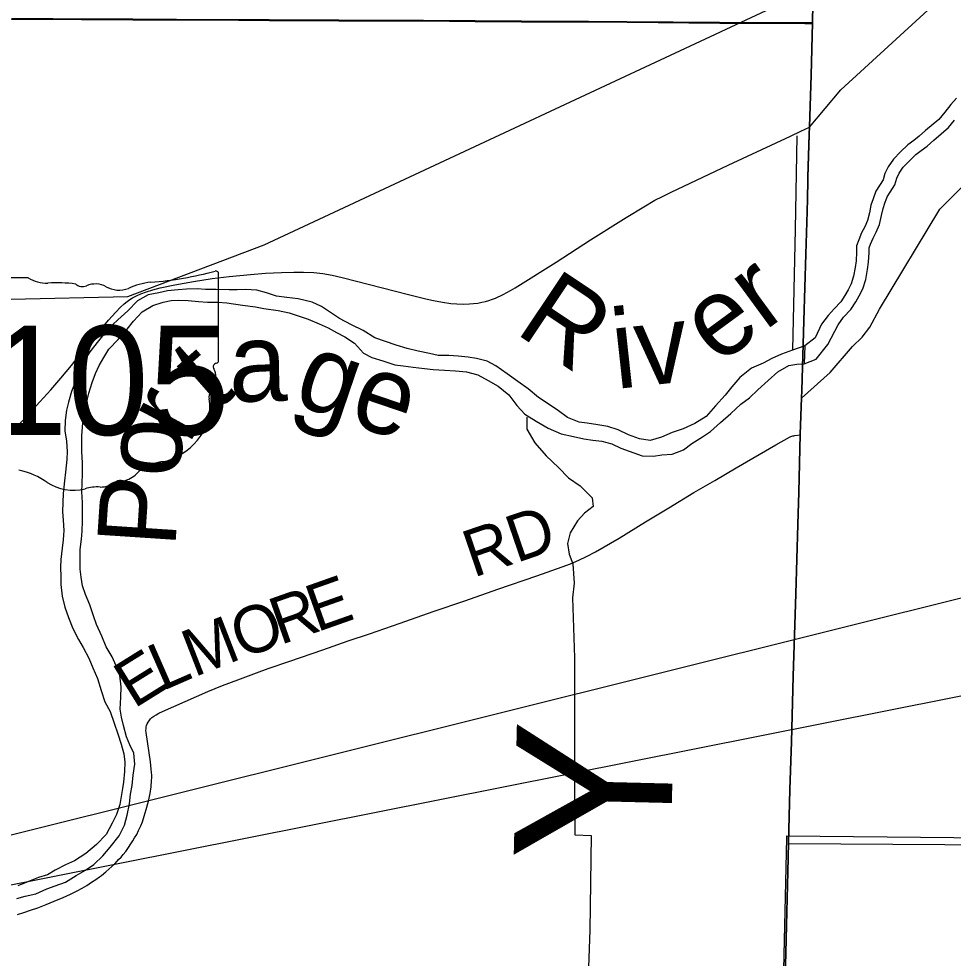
# Model space of a CAD drawing. Extents: x 0 to 34, y 0 to 22.
# Drawn here: x 6.172 to 7.301, y 17.366 to 18.499 of the extents above; entities that cross this region are included whole.
import ezdxf

# ---------------------------------------------------------------- set-up
doc = ezdxf.new("R2010")
doc.units = 0
for name, color, linetype in [('Default', 7, 'Continuous'), ('GM_X_County_Road', 7, 'Continuous'), ('GM_X_County_Text', 7, 'Continuous'), ('GM_X_Major_River', 7, 'Continuous'), ('GM_X_Major_River_Text', 7, 'Continuous'), ('GM_X_Minor_River', 7, 'Continuous'), ('GM_X_Rail_Line', 7, 'Continuous'), ('GM_X_Section', 7, 'Continuous'), ('GM_X_State_Location', 7, 'Continuous'), ('GM_X_State_Route', 7, 'Continuous'), ('GM_X_State_Shield', 7, 'Continuous'), ('GM_X_Township_Road', 7, 'Continuous'), ('GM_X_Township_Road_Text', 7, 'Continuous'), ('GM_X_US_Route', 7, 'Continuous'), ('SH_Cut_Line', 7, 'Continuous'), ('SH_Text', 7, 'Continuous')]:
    doc.layers.add(name, color=color, linetype=linetype)

msp = doc.modelspace()

# ---------------------------------------------------------------- linework, layer by layer
at = {"layer": 'Default'}
for points in [[(6.164, 18.4994), (6.2138, 18.4993), (6.2479, 18.4991), (6.2852, 18.4989), (6.3101, 18.4989), (6.3629, 18.4987), (6.4375, 18.4981), (6.4748, 18.498), (6.5588, 18.4976), (6.6613, 18.4974), (6.7235, 18.4969), (6.7794, 18.4965), (6.8603, 18.4961), (6.9069, 18.4959), (7.0188, 18.4948), (7.0871, 18.4945), (7.1214, 18.4945), (7.1309, 18.4945), (7.1309, 18.4967), (7.1325, 18.5729)], [(7.1325, 18.5729), (7.1309, 18.4967), (7.1309, 18.4945), (7.1292, 18.4315), (7.1272, 18.3691), (7.1269, 18.36), (7.1254, 18.3087), (7.1253, 18.3041), (7.1248, 18.2823), (7.1245, 18.2668), (7.1228, 18.2155), (7.1205, 18.1347), (7.118, 18.0508), (7.1177, 18.0419), (7.1163, 17.998), (7.1163, 17.9976), (7.1144, 17.9281), (7.1133, 17.8892), (7.1108, 17.8053), (7.1078, 17.7059), (7.1055, 17.6267), (7.1037, 17.5692), (7.1025, 17.521), (7.102, 17.5046), (7.1011, 17.4697), (7.0999, 17.4216), (7.0987, 17.3718), (7.096, 17.2678)], [(7.096, 17.2678), (7.0987, 17.3718), (7.0999, 17.4216), (7.1011, 17.4697), (7.102, 17.5046), (7.1025, 17.521), (7.1037, 17.5692), (7.1055, 17.6267), (7.1078, 17.7059), (7.1108, 17.8053), (7.1133, 17.8892), (7.1144, 17.9281), (7.1163, 17.9976), (7.1163, 17.998), (7.1177, 18.0419), (7.118, 18.0508), (7.1205, 18.1347), (7.1228, 18.2155), (7.1245, 18.2668), (7.1248, 18.2823), (7.1253, 18.3041), (7.1254, 18.3087), (7.1269, 18.36), (7.1272, 18.3691), (7.1292, 18.4315), (7.1309, 18.4945), (7.1214, 18.4945), (7.0871, 18.4945), (7.0188, 18.4948), (6.9069, 18.4959), (6.8603, 18.4961), (6.7794, 18.4965), (6.7235, 18.4969), (6.6613, 18.4974), (6.5588, 18.4976), (6.4748, 18.498), (6.4375, 18.4981), (6.3629, 18.4987), (6.3101, 18.4989), (6.2852, 18.4989), (6.2479, 18.4991), (6.2138, 18.4993), (6.164, 18.4994)]]:
    msp.add_lwpolyline(points, dxfattribs=at)
at = {"layer": 'GM_X_County_Road'}
for points in [[(6.1298, 18.4993), (6.1642, 18.4989), (6.214, 18.4988), (6.2482, 18.4985), (6.2855, 18.4984), (6.3103, 18.4983), (6.3632, 18.4981), (6.4378, 18.4976), (6.4751, 18.4974), (6.559, 18.4971), (6.6616, 18.4969), (6.7237, 18.4963), (6.7797, 18.4959), (6.8605, 18.4956), (6.9071, 18.4953), (7.019, 18.4943), (7.0874, 18.494), (7.1216, 18.4939), (7.1311, 18.4939)], [(7.1179, 18.0413), (7.1522, 18.0724), (7.1795, 18.1039), (7.1909, 18.1153), (7.2004, 18.1271), (7.2118, 18.1488), (7.2847, 18.2696), (7.4268, 18.4117)], [(7.1023, 17.5041), (8.1067, 17.4977), (8.5995, 17.493)]]:
    msp.add_lwpolyline(points, dxfattribs=at)
at = {"layer": 'GM_X_Major_River'}
msp.add_line((7.1219, 18.1046), (7.1211, 18.0831), dxfattribs=at)
for points in [[(7.3051, 18.4037), (7.2979, 18.3961), (7.2907, 18.3866), (7.2835, 18.3778)], [(7.2835, 18.3778), (7.2676, 18.3645), (7.2597, 18.3576), (7.2533, 18.3526), (7.2461, 18.3473), (7.2374, 18.3389), (7.2287, 18.3301), (7.2223, 18.3206), (7.2185, 18.3126), (7.2163, 18.305), (7.2121, 18.2981), (7.2076, 18.2913), (7.2042, 18.2821), (7.2016, 18.2745), (7.1997, 18.2654), (7.1975, 18.2559), (7.1941, 18.2483), (7.1903, 18.2411), (7.1869, 18.2327), (7.1843, 18.2255), (7.1843, 18.2179), (7.1836, 18.2072), (7.1825, 18.1993), (7.1807, 18.1886), (7.1777, 18.1795), (7.1739, 18.1723), (7.1701, 18.1654), (7.1652, 18.1578), (7.1573, 18.1494), (7.1501, 18.1414), (7.1419, 18.1308), (7.1342, 18.1144), (7.1219, 18.1046)], [(7.2953, 18.3682), (7.3026, 18.3772)], [(7.1211, 18.0831), (7.1355, 18.0885), (7.1495, 18.1064), (7.162, 18.1301), (7.1684, 18.1391), (7.1772, 18.1484), (7.1832, 18.1576), (7.1873, 18.1651), (7.1917, 18.1736), (7.1954, 18.1849), (7.1975, 18.1969), (7.1987, 18.2057), (7.1995, 18.2174), (7.1995, 18.2228), (7.2011, 18.2272), (7.2041, 18.2347), (7.2078, 18.2417), (7.2119, 18.251), (7.2145, 18.2621), (7.2162, 18.2705), (7.2185, 18.277), (7.2212, 18.2844), (7.2249, 18.29), (7.2303, 18.2988), (7.2327, 18.3072), (7.2355, 18.3131), (7.2405, 18.3204), (7.248, 18.3281), (7.2559, 18.3357), (7.2624, 18.3405), (7.2693, 18.3458), (7.2775, 18.3529), (7.2953, 18.3682)], [(7.1219, 18.1046), (7.107, 18.0994), (7.0936, 18.0948), (7.0817, 18.0894), (7.0714, 18.0836), (7.0572, 18.0778), (7.0431, 18.0664), (7.0335, 18.0553), (7.0257, 18.0452), (7.0137, 18.0322), (7.0024, 18.0192), (6.9889, 18.0108), (6.9747, 18.0043), (6.9617, 18.0001), (6.9487, 17.9943), (6.935, 17.9905), (6.9222, 17.9923), (6.9087, 17.9972), (6.8963, 18.0032), (6.8839, 18.0073), (6.8718, 18.0095), (6.859, 18.0113), (6.8492, 18.0127), (6.8353, 18.0183), (6.8242, 18.0262), (6.813, 18.0337), (6.8003, 18.0423), (6.7877, 18.0529), (6.7751, 18.0615), (6.7624, 18.071), (6.7486, 18.0804), (6.7382, 18.0863), (6.7254, 18.0893), (6.7152, 18.0911), (6.7031, 18.0921), (6.6918, 18.0928), (6.6789, 18.0931), (6.6683, 18.0956), (6.6548, 18.0982), (6.6416, 18.1016), (6.6284, 18.1053), (6.6153, 18.1098), (6.6025, 18.1143), (6.5884, 18.123), (6.5741, 18.1302), (6.5599, 18.1377), (6.5503, 18.144), (6.538, 18.1523), (6.5267, 18.1575), (6.5098, 18.1613), (6.4962, 18.1632), (6.4837, 18.1646), (6.4717, 18.1687), (6.4599, 18.1717), (6.4461, 18.1727), (6.4362, 18.1722), (6.4264, 18.1721), (6.4109, 18.1728), (6.398, 18.1728), (6.3878, 18.1734), (6.3749, 18.173), (6.365, 18.1724), (6.3521, 18.1712), (6.3418, 18.1688), (6.3289, 18.1661), (6.3158, 18.1588), (6.3042, 18.147), (6.2922, 18.1362), (6.2801, 18.1248), (6.2688, 18.1106), (6.2583, 18.0976), (6.2504, 18.0845), (6.2448, 18.0725), (6.2415, 18.0627), (6.2362, 18.0496), (6.2325, 18.0367), (6.23, 18.0269), (6.2286, 18.0145), (6.2282, 18.0019), (6.2302, 17.9897), (6.231, 17.9772), (6.2304, 17.9673), (6.2289, 17.9522), (6.2275, 17.9416), (6.226, 17.9265), (6.2254, 17.9045), (6.226, 17.8942), (6.2268, 17.8817), (6.2261, 17.8707), (6.2247, 17.8605), (6.2233, 17.8468), (6.223, 17.8374), (6.2231, 17.826), (6.2233, 17.8165), (6.2248, 17.8024), (6.2279, 17.7894), (6.2325, 17.7768), (6.2379, 17.7634), (6.2447, 17.7503), (6.2502, 17.7407), (6.257, 17.7276)], [(6.3107, 17.5866), (6.3126, 17.5999), (6.3114, 17.6128), (6.3067, 17.6232), (6.3024, 17.6328), (6.299, 17.6465), (6.2966, 17.6564), (6.2949, 17.6663), (6.2956, 17.6807), (6.2963, 17.6929), (6.2944, 17.707), (6.2901, 17.7185), (6.2851, 17.7292), (6.2782, 17.7415), (6.2728, 17.7542), (6.2664, 17.7684), (6.2629, 17.7787), (6.2583, 17.7921), (6.2529, 17.8047), (6.2494, 17.8151), (6.2477, 17.8254), (6.2468, 17.8349), (6.2468, 17.8485), (6.2467, 17.8588), (6.2481, 17.8713), (6.2491, 17.8811), (6.2494, 17.8929), (6.2493, 17.9039), (6.2496, 17.9156), (6.2488, 17.9286), (6.249, 17.9381), (6.2493, 17.9509), (6.2493, 17.9635), (6.2488, 17.9771), (6.2486, 17.9961), (6.2497, 18.0117), (6.2515, 18.0226), (6.2537, 18.034), (6.257, 18.0475), (6.2611, 18.0603), (6.2652, 18.0712), (6.2696, 18.081), (6.2751, 18.0907), (6.2814, 18.1008), (6.2927, 18.1123), (6.3032, 18.1248), (6.3112, 18.1345), (6.3216, 18.1458), (6.3343, 18.1534), (6.3468, 18.1573), (6.3564, 18.1594), (6.3658, 18.1599), (6.3769, 18.1592), (6.3897, 18.1582), (6.4002, 18.1575), (6.4127, 18.1572), (6.4237, 18.1566), (6.4426, 18.1539), (6.4584, 18.1516), (6.4686, 18.1498), (6.4856, 18.1475), (6.4991, 18.1445), (6.5052, 18.1424), (6.5221, 18.1367), (6.5352, 18.1311), (6.546, 18.1263), (6.5561, 18.1207), (6.5662, 18.1156), (6.5778, 18.1077), (6.5888, 18.0957), (6.5989, 18.0905), (6.6121, 18.0864), (6.6267, 18.0818), (6.6365, 18.0805), (6.6486, 18.079), (6.6626, 18.0775), (6.6728, 18.0762), (6.6864, 18.0751), (6.7, 18.0744), (6.7132, 18.0733), (6.7268, 18.0695), (6.7395, 18.0628), (6.7514, 18.056), (6.7644, 18.0455), (6.774, 18.0327), (6.7837, 18.0223), (6.7973, 18.0139), (6.8119, 18.0052), (6.8273, 17.9984), (6.8423, 17.9954), (6.8548, 17.9924), (6.8657, 17.9906), (6.8767, 17.9896), (6.8887, 17.9863), (6.8995, 17.9811), (6.9254, 17.9717), (6.9391, 17.9714), (6.949, 17.9731), (6.9615, 17.9739), (6.9752, 17.9793), (6.9853, 17.9866)], [(6.9853, 17.9866), (6.9983, 17.995), (7.008, 18.0012), (7.02, 18.012), (7.0324, 18.023), (7.0444, 18.0341), (7.0548, 18.0419), (7.0649, 18.0515), (7.0773, 18.0629), (7.0893, 18.0733), (7.1023, 18.0809), (7.1122, 18.0826), (7.1211, 18.0831)], [(6.257, 17.7276), (6.2621, 17.7161), (6.2674, 17.7031), (6.272, 17.6885), (6.2766, 17.6751), (6.2827, 17.6632), (6.2877, 17.6494), (6.2919, 17.6364), (6.2961, 17.6238), (6.2992, 17.612), (6.3005, 17.6021), (6.3002, 17.5907), (6.2989, 17.5778), (6.2976, 17.5703), (6.2947, 17.551), (6.2906, 17.5389), (6.2854, 17.5284), (6.2779, 17.515), (6.2662, 17.5027), (6.2535, 17.492), (6.2396, 17.4829), (6.2289, 17.4782), (6.2166, 17.4717), (6.207, 17.4662), (6.1963, 17.463), (6.1841, 17.458), (6.1715, 17.453)], [(6.1703, 17.4375), (6.18, 17.4403), (6.1932, 17.4434), (6.2062, 17.4491), (6.2165, 17.4527), (6.2287, 17.4573), (6.2418, 17.4654), (6.253, 17.4719), (6.263, 17.4785), (6.2738, 17.4892), (6.2828, 17.4997), (6.2938, 17.5134), (6.3001, 17.5262), (6.3035, 17.5382), (6.3061, 17.5518), (6.3075, 17.5636), (6.3093, 17.5738), (6.3107, 17.5866)]]:
    msp.add_lwpolyline(points, dxfattribs=at)
at = {"layer": 'GM_X_Minor_River'}
for points in [[(7.1074, 18.0998), (7.1106, 18.2451), (7.1123, 18.3581)], [(6.7861, 18.0184), (6.7861, 18.004), (6.7956, 17.9874), (6.8092, 17.9719), (6.8244, 17.9579), (6.8362, 17.9454), (6.8503, 17.9356), (6.8651, 17.9212), (6.866, 17.9106), (6.8556, 17.9028), (6.8474, 17.8936), (6.8383, 17.879), (6.835, 17.8662), (6.8373, 17.8532), (6.8415, 17.8417), (6.8432, 17.8181), (6.8413, 17.8003), (6.8437, 17.7282), (6.8437, 17.5919), (6.844, 17.5145), (6.8637, 17.5136), (6.862, 17.3994), (6.8593, 17.321)]]:
    msp.add_lwpolyline(points, dxfattribs=at)
at = {"layer": 'GM_X_Rail_Line'}
msp.add_lwpolyline([(5.1236, 17.5022), (5.2885, 17.5882), (5.4372, 17.6568), (5.858, 17.9153), (6.1629, 18.1611), (6.3042, 18.1643), (6.4687, 18.2265), (7.1295, 18.535)], dxfattribs=at)
at = {"layer": 'GM_X_Section'}
msp.add_lwpolyline([(7.1, 17.5132), (8.1087, 17.5031), (8.0805, 16.4987), (7.0767, 16.5008), (7.0769, 16.5061), (7.0999, 17.5106)], close=True, dxfattribs=at)
at = {"layer": 'GM_X_State_Route'}
for points in [[(7.1275, 18.3685), (7.1654, 18.4136), (7.3608, 18.5932), (7.4758, 18.6969), (7.6618, 18.8326), (7.7258, 18.8796), (7.8269, 18.9622), (7.9458, 19.0794), (8.0941, 19.2274), (8.2454, 19.3754), (8.3174, 19.4447), (8.6611, 19.7985), (8.7135, 19.8476), (8.8036, 19.9332), (8.8247, 19.9539), (8.842, 19.9695), (8.8812, 19.988), (8.9, 19.9963)], [(6.1309, 17.9652), (6.1765, 18.0137), (6.1979, 18.0369), (6.2112, 18.0517), (6.2233, 18.0657), (6.2361, 18.081), (6.2442, 18.0912), (6.2513, 18.0999), (6.2684, 18.1205), (6.2809, 18.1358), (6.2892, 18.145), (6.2953, 18.1512), (6.2998, 18.1553), (6.3034, 18.1582), (6.3067, 18.1606), (6.3098, 18.1625), (6.3146, 18.1651), (6.3197, 18.1674), (6.3266, 18.17), (6.3343, 18.1723), (6.3433, 18.1746), (6.3609, 18.1782), (6.3835, 18.1824), (6.4062, 18.1858), (6.4266, 18.1883), (6.4525, 18.1909), (6.4705, 18.1923), (6.4897, 18.1933), (6.5046, 18.1937), (6.5164, 18.1936), (6.5287, 18.193), (6.5398, 18.1918), (6.5508, 18.19), (6.5629, 18.1873), (6.643, 18.1668), (6.6641, 18.1614), (6.6732, 18.1593), (6.6842, 18.1572), (6.6941, 18.1558), (6.7016, 18.1552), (6.7091, 18.155), (6.7167, 18.1552), (6.7218, 18.1556), (6.727, 18.1563), (6.7316, 18.1572), (6.7362, 18.1583), (6.7403, 18.1594), (6.7444, 18.1608), (6.7482, 18.1623), (6.7515, 18.1638), (6.7543, 18.1651), (6.7575, 18.1667), (6.762, 18.169), (6.7662, 18.1714), (6.7719, 18.1747), (6.8215, 18.2057), (6.8629, 18.2325), (6.9061, 18.2597), (6.9274, 18.2726), (6.9408, 18.2803), (6.9499, 18.2851), (6.9603, 18.2901), (7.0293, 18.3229), (7.1043, 18.3579), (7.117, 18.3637), (7.1275, 18.3685)]]:
    msp.add_lwpolyline(points, dxfattribs=at)
at = {"layer": 'GM_X_State_Shield'}
for p, q in [((6.4138, 18.087), (6.4138, 18.1917)), ((6.1839, 18.1867), (6.0874, 18.1867)), ((6.4137, 18.087), (6.4138, 18.087))]:
    msp.add_line(p, q, dxfattribs=at)
for centre, major_axis, start_param, end_param in [((6.2964, 18.4595), (0.3495, 0), 4.814394, 5.042369), ((6.4101, 18.1921), (0.00367, 0), 6.141152, 7.989035), ((6.2069, 18.2099), (0.037, 0), 4.042523, 4.731795), ((6.2192, 18.0743), (0.133, 0), 1.404758, 1.657858), ((6.2494, 18.1847), (0.0107, 0), 3.836095, 5.185415), ((6.2651, 18.1616), (0.0222, 0), 0.950623, 2.079405), ((6.3409, 18.1256), (0.0703, 0), 1.699011, 2.107814), ((6.2937, 18.1933), (0.0267, 0), 4.081561, 5.145723), ((6.4098, 18.0866), (0.00393, 0), 5.05454, 6.418171), ((6.4129, 18.0793), (0.00568, 0), 1.883978, 3.671073), ((6.3768, 18.066), (0.0341, 0), 5.934695, 6.695948), ((6.4269, 18.0432), (0.0248, 0), 2.387724, 3.262537), ((6.3159, 18.0298), (0.0874, 0), 5.101752, 6.440018), ((6.3528, 17.9269), (0.0479, 0), 1.647645, 2.488434), ((6.1532, 17.8932), (0.079, 0), 0.823519, 1.323587), ((6.2921, 17.9637), (0.0282, 0), 4.937069, 5.64225), ((6.2386, 17.9706), (0.0501, 0), 4.026481, 4.996735), ((6.2712, 17.9556), (0.0267, 0), 4.691044, 5.507374), ((6.2953, 17.9362), (0.00752, 0), 1.147584, 2.315152), ((6.2675, 17.9014), (0.0412, 0), 1.495662, 1.94098)]:
    msp.add_ellipse(centre, major_axis=major_axis, ratio=0.8, start_param=start_param, end_param=end_param, dxfattribs=at)
at = {"layer": 'GM_X_Township_Road'}
msp.add_lwpolyline([(6.171, 17.4183), (6.1784, 17.4206), (6.1865, 17.4233), (6.1953, 17.4264), (6.2054, 17.4304), (6.2152, 17.4342), (6.2261, 17.4388), (6.2351, 17.4428), (6.243, 17.4467), (6.2492, 17.4502), (6.2547, 17.4534), (6.2604, 17.4571), (6.2656, 17.4607), (6.27, 17.4638), (6.2724, 17.4655), (6.2778, 17.4699), (6.2848, 17.4761), (6.2884, 17.4796), (6.2914, 17.4827), (6.2931, 17.4845), (6.296, 17.4876), (6.2987, 17.4908), (6.3016, 17.4944), (6.3057, 17.5003), (6.3071, 17.5024), (6.3102, 17.5071), (6.3124, 17.5108), (6.315, 17.515), (6.3172, 17.5197), (6.3199, 17.5253), (6.3217, 17.53), (6.3241, 17.5371), (6.3264, 17.5449), (6.3291, 17.5551), (6.3311, 17.5643), (6.3323, 17.5724), (6.3328, 17.5799), (6.333, 17.5832), (6.333, 17.5865), (6.3328, 17.5897), (6.3324, 17.5937), (6.3314, 17.6024), (6.3263, 17.638), (6.3261, 17.6402), (6.3262, 17.6426), (6.3265, 17.6447), (6.3269, 17.6464), (6.3276, 17.6484), (6.3287, 17.6504), (6.3298, 17.6522), (6.3314, 17.6543), (6.3333, 17.656), (6.3354, 17.6576), (6.3383, 17.6593), (6.3415, 17.6611), (6.346, 17.6632), (6.4006, 17.6874), (6.4183, 17.6947), (6.4369, 17.7016), (6.4597, 17.7099), (6.4737, 17.7151), (6.4997, 17.7242), (6.5395, 17.7378), (6.5701, 17.7484), (6.596, 17.7572), (6.633, 17.7699), (6.673, 17.7839), (6.7112, 17.797), (6.7511, 17.8109), (6.7981, 17.8272), (6.8287, 17.8378), (6.8386, 17.8415), (6.849, 17.8459), (6.858, 17.8502), (6.8689, 17.856), (6.8974, 17.8727), (6.9293, 17.8922), (6.9574, 17.9093), (6.9877, 17.9277), (7.013, 17.9423), (7.0388, 17.9573), (7.0867, 17.9851), (7.1033, 17.9944), (7.1049, 17.9951), (7.106, 17.9956), (7.1073, 17.996), (7.1084, 17.9962), (7.1098, 17.9964), (7.1165, 17.9971)], dxfattribs=at)
at = {"layer": 'GM_X_US_Route'}
for points in [[(7.1311, 18.4939), (7.1312, 18.4962), (7.1327, 18.5723)], [(7.0962, 17.2672), (7.0989, 17.3713), (7.1002, 17.421), (7.1014, 17.4692), (7.1023, 17.5041), (7.1027, 17.5205), (7.1039, 17.5686), (7.1057, 17.6261), (7.108, 17.7053), (7.111, 17.8048), (7.1136, 17.8887), (7.1146, 17.9275), (7.1165, 17.9971), (7.1179, 18.0413), (7.1182, 18.0503), (7.1207, 18.1341), (7.1231, 18.215), (7.1248, 18.2662), (7.125, 18.2818), (7.1256, 18.3035), (7.1256, 18.3082), (7.1272, 18.3594), (7.1275, 18.3685), (7.1294, 18.4309), (7.1311, 18.4939)]]:
    msp.add_lwpolyline(points, dxfattribs=at)
at = {"layer": 'SH_Cut_Line'}
for points in [[(7.096, 17.2678), (7.0987, 17.3718), (7.0999, 17.4216), (7.1011, 17.4697), (7.102, 17.5046), (7.1025, 17.521), (7.1037, 17.5692), (7.1055, 17.6267), (7.1078, 17.7059), (7.1108, 17.8053), (7.1133, 17.8892), (7.1144, 17.9281), (7.1163, 17.9976), (7.1163, 17.998), (7.1177, 18.0419), (7.118, 18.0508), (7.1205, 18.1347), (7.1228, 18.2155), (7.1245, 18.2668), (7.1248, 18.2823), (7.1253, 18.3041), (7.1254, 18.3087), (7.1269, 18.36), (7.1272, 18.3691), (7.1292, 18.4315), (7.1309, 18.4945), (7.1309, 18.4967), (7.1325, 18.5729)], [(7.1325, 18.5729), (7.1309, 18.4967), (7.1309, 18.4945), (7.1292, 18.4315), (7.1272, 18.3691), (7.1269, 18.36), (7.1254, 18.3087), (7.1253, 18.3041), (7.1248, 18.2823), (7.1245, 18.2668), (7.1228, 18.2155), (7.1205, 18.1347), (7.118, 18.0508), (7.1177, 18.0419), (7.1163, 17.998), (7.1163, 17.9976), (7.1144, 17.9281), (7.1133, 17.8892), (7.1108, 17.8053), (7.1078, 17.7059), (7.1055, 17.6267), (7.1037, 17.5692), (7.1025, 17.521), (7.102, 17.5046), (7.1011, 17.4697), (7.0999, 17.4216), (7.0987, 17.3718), (7.096, 17.2678)]]:
    msp.add_lwpolyline(points, dxfattribs=at)
at = {"layer": 'SH_Text'}
msp.add_lwpolyline([(9.3111, 18.299), (4.9771, 17.2181), (9.3111, 18.0801)], close=True, dxfattribs=at)

# ---------------------------------------------------------------- texts
at = {"layer": 'GM_X_County_Text'}
msp.add_text('Y', height=0.1894, rotation=88.6072, dxfattribs=at).set_placement((6.9594, 17.4802))
at = {"layer": 'GM_X_Major_River_Text'}
for s, height, rotation, p in [('er', 0.09475, 36.2255, (7.0161, 18.0803)), ('R', 0.0948, 326.2233, (6.77, 18.1212)), ('iv', 0.09475, 6.2243, (6.8936, 18.0525)), ('a', 0.0948, 1.2236, (6.427, 18.0369)), ('t', 0.0948, 41.2253, (6.4097, 18.0238)), ('ge', 0.09475, 341.2231, (6.5015, 18.0347)), ('r', 0.0948, 61.2258, (6.3777, 17.9843)), ('Po', 0.09476, 86.2254, (6.3614, 17.8601))]:
    msp.add_text(s, height=height, rotation=rotation, dxfattribs=at).set_placement(p)
at = {"layer": 'GM_X_State_Location'}
for s in ['s', 'r']:
    msp.add_text(s, height=0.000189, dxfattribs=at).set_placement((6.2453, 18.0699))
msp.add_text('105', height=0.000189, rotation=0, dxfattribs=at).set_placement((6.1784, 18.0561))
at = {"layer": 'GM_X_State_Shield'}
msp.add_text('105', height=0.13184, dxfattribs=at).set_placement((6.1333, 17.9972))
at = {"layer": 'GM_X_Township_Road_Text'}
for s, height, rotation, p in [('RD', 0.05682, 18.8993, (6.7214, 17.8246)), ('E', 0.0568, 19.4556, (6.5323, 17.7588)), ('R', 0.0568, 19.4039, (6.4883, 17.7433)), ('O', 0.0568, 19.4752, (6.4411, 17.7266)), ('M', 0.0568, 21.2793, (6.3841, 17.7044)), ('E', 0.0568, 31.8641, (6.3116, 17.6662)), ('L', 0.0568, 23.6488, (6.3458, 17.6876))]:
    msp.add_text(s, height=height, rotation=rotation, dxfattribs=at).set_placement(p)

doc.saveas('drawing.dxf')
